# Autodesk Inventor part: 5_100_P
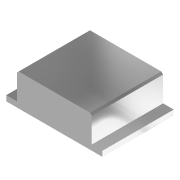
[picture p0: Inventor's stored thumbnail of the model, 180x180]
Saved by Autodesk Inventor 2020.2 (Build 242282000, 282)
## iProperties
Created: 2011-11
Part Number: 5_100_P
Material: Ogólny
Document SubType Name: Modeling
Designer: F.Stasiak
Density: 1 g/cm^3
Appearance: Chrom — polerowany
Manager: www.cadconsulting.pl
Company: Fabian Stasiak CAD Consulting
Author: F.Stasiak
Subject: Zbiór ćwiczeń. Autodesk Inventor 2020. Kurs podstawowy
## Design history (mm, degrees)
sketch "Szkic1"
  geometry: L1 (-135, -100)-(135, -100); L2 (135, -100)-(135, 100); L3 (135, 100)-(-135, 100); L4 (-135, 100)-(-135, -100); 3 further points
  constraints: 8 end point, 2 midpoint, 2 parallel, 1 horizontal, 1 horizontal alignment, 1 perpendicular, 1 vertical alignment
  dimensions: "d0" = 270 distance of L3.end L2.end; "d1" = 200 distance of L2.end L1.end
extrude "Wyciągnięcie proste1" new body sketch "Szkic1" distance "d2" = 90; taper "d3" = 0 deg
sketch "Szkic2"
  geometry: L1 (0, 15)-(30, 15); L2 (30, 15)-(30, 90); L3 (270, 90)-(0, 90) reference; L4 (270, 15)-(240, 15); L5 (240, 15)-(240, 90); L6 (0, 0)-(270, 0) reference; L7 (0, 0)-(0, 90) reference; L8 (270, 0)-(270, 90) reference; 1 further point
  constraints: 8 end point, 4 point on line, 2 collinear, 2 perpendicular, 1 horizontal, 1 parallel
  dimensions: "d4" = 15 distance between parallel lines of L4 L6; "d5" = 30 distance of L4.start L4.end
extrude "Wyciągnięcie proste2" cut sketch "Szkic2" extent not by distance; stored distance "d6" = 183.75; taper "d7" = 0 deg
chamfer "Faza1" distance "d8" = 5; stored, may be unused: second distance "d9" = 2, angle "d10" = 45 deg
node "Bryła1"
